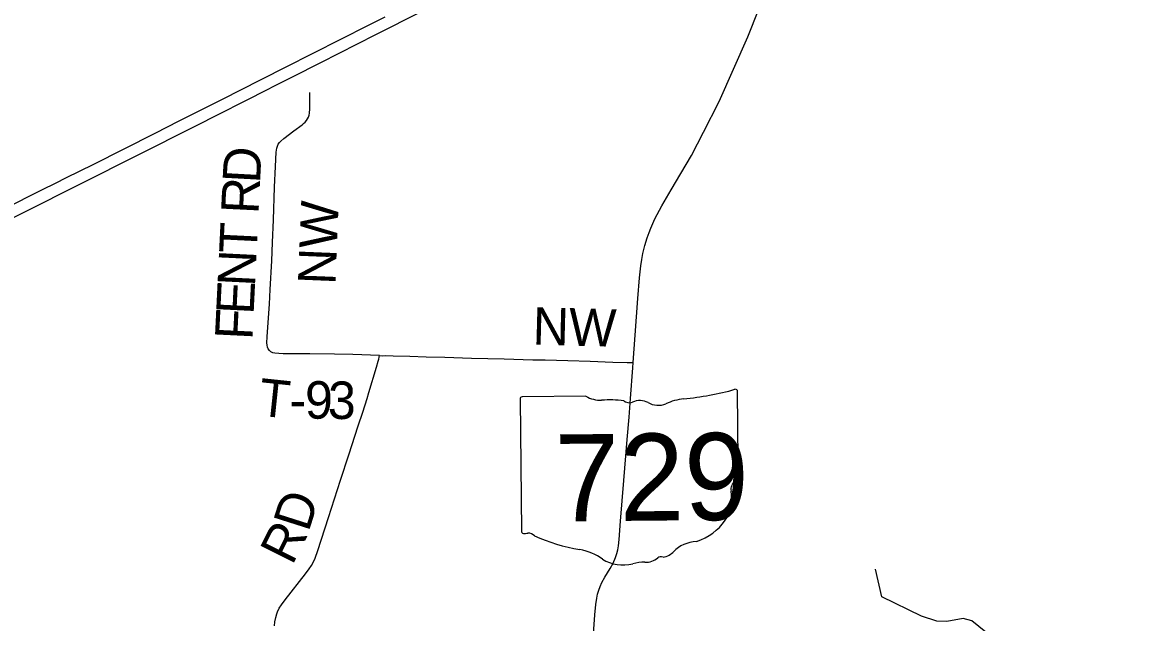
# Model space of a CAD drawing. Extents: x -51392 to 1635000, y 156707 to 696232.
# Drawn here: x 99291 to 108334, y 518897 to 523695 of the extents above; entities that cross this region are included whole.
import ezdxf

# ---------------------------------------------------------------- set-up
doc = ezdxf.new("R2010")
doc.units = 0
for name, color, linetype in [('GM_X_Interstate_Route', 7, 'Continuous'), ('GM_X_Minor_River', 7, 'Continuous'), ('GM_X_State_Route', 7, 'Continuous'), ('GM_X_State_Shield', 7, 'Continuous'), ('GM_X_Township_Road', 7, 'Continuous'), ('GM_X_Township_Road_Text', 7, 'Continuous')]:
    doc.layers.add(name, color=color, linetype=linetype)

msp = doc.modelspace()

# ---------------------------------------------------------------- linework, layer by layer
at = {"layer": 'GM_X_Interstate_Route'}
for points in [[(98288.9, 521664.8), (99299.2, 522175.3), (100672.6, 522866.2), (101261.3, 523166.3), (101288.6, 523180.1), (101449.2, 523261.5), (101677, 523376.8), (102116.2, 523598.7), (104332.5, 524719.6), (104554.7, 524832), (104752.9, 524932.3), (105459.5, 525289.9), (105516, 525318)], [(99138.8, 522202.1), (99451.2, 522359.7), (99553.2, 522411.1), (99642.5, 522456.9), (99854.4, 522560.5), (100352.1, 522811.7), (100543, 522908.6), (100906.6, 523091.8), (101026.5, 523152.4), (101392.8, 523339.4), (102056.5, 523673.7), (102190.2, 523741)]]:
    msp.add_lwpolyline(points, dxfattribs=at)
at = {"layer": 'GM_X_Minor_River'}
for points in [[(106161.9, 519100.6), (106111, 519322.7)], [(108342.2, 518202.7), (108302.5, 518267.1), (108220.7, 518345.9), (107975, 518510.1), (107850.9, 518565.1), (107718.6, 518588.1), (107533.7, 518555.4), (107475.5, 518559.9), (107253.2, 518631.7), (107175.2, 518672.3), (106881.8, 518911), (106813.7, 518929.6), (106681, 518904.5), (106600.8, 518907.1), (106478.6, 518948.1), (106161.9, 519100.6)]]:
    msp.add_lwpolyline(points, dxfattribs=at)
at = {"layer": 'GM_X_State_Route'}
msp.add_lwpolyline([(103852.3, 518729.9), (103868.1, 518959), (103875.4, 519040.9), (103882.5, 519089.9), (103889.5, 519122.2), (103898.6, 519154.1), (103910, 519185.2), (103923.8, 519215.2), (103947.7, 519258.7), (103989.9, 519329), (104012.6, 519372.2), (104031.7, 519417.1), (104042.1, 519447.8), (104050.3, 519479.1), (104056.6, 519511), (104062.5, 519559.4), (104073.7, 519706.5), (104098.9, 520033.6), (104126.4, 520360.4), (104140.5, 520540.2), (104152.3, 520687.4), (104171.5, 520932.6), (104174.6, 520976.2), (104190.7, 521194.3), (104211.7, 521488.7), (104224.9, 521652.2), (104235, 521750.3), (104242.1, 521799.2), (104251.8, 521847.7), (104266.5, 521911.5), (104285.9, 521974.6), (104300.8, 522015.7), (104314.5, 522051.3), (104330.1, 522088.7), (104347.5, 522124.3), (104402.3, 522229.6), (104478, 522357.8), (104554.3, 522486.7), (104639.1, 522632.9), (104737.4, 522817.8), (104861.8, 523064.3), (105090.7, 523580.8), (105178.9, 523801.9)], dxfattribs=at)
at = {"layer": 'GM_X_State_Shield'}
for p, q in [((105014.5, 520191.6), (105009.3, 520744.3)), ((103269.6, 520683.6), (103279.5, 519627)), ((103796.2, 520706.7), (103286.6, 520701.9)), ((105014.3, 520191.7), (105014.5, 520191.6))]:
    msp.add_line(p, q, dxfattribs=at)
for centre, major_axis, start_param, end_param in [((104376.2, 522152.8), (1845.4, 17.3), 4.814394, 5.042369), ((104990, 520746.4), (19.4, 0.2), 6.141152, 7.989035), ((103289.5, 520686), (20.2, 0.2), 1.712693, 3.28349), ((103916.4, 520830.5), (195.5, 1.8), 4.042523, 4.731795), ((103987.9, 520115.3), (702, 6.6), 1.404758, 1.657858), ((104141.8, 520699.5), (56.4, 0.5), 3.836095, 5.185415), ((104225.8, 520578.1), (117.3, 1.1), 0.950623, 2.079405), ((104375.6, 520747.1), (141.1, 1.3), 4.081561, 5.145723), ((104628.1, 520391.8), (371.3, 3.5), 1.699011, 2.107814), ((104993.9, 520189.2), (20.7, 0.2), 5.05454, 6.418171), ((105010.4, 520150.9), (30, 0.3), 1.883978, 3.671073), ((104820.3, 520079.3), (180, 1.7), 5.934695, 6.695948), ((105086.1, 519960.9), (130.9, 1.2), 2.387724, 3.262537), ((104500.9, 519885.1), (461.6, 4.3), 5.101752, 6.440018), ((103299.7, 519624.8), (20.3, 0.2), 3.00124, 4.508301), ((103301.7, 519733), (155.2, 1.5), 4.665946, 4.897461), ((103335.1, 519566.5), (56, 0.5), 0.519207, 1.627899), ((104032.7, 520522.5), (1332.6, 12.5), 4.195997, 4.488961), ((103648.2, 519155.7), (417, 3.9), 0.823519, 1.323587), ((104700.6, 519343.7), (252.8, 2.4), 1.647645, 2.488434), ((104095.3, 519568.4), (264.6, 2.5), 4.026481, 4.996735), ((104251.6, 519204.6), (217.4, 2), 1.495662, 1.94098), ((104268.3, 519490.9), (141, 1.3), 4.691044, 5.507374), ((104396.8, 519389.8), (39.7, 0.4), 1.147584, 2.315152), ((104378.5, 519534.9), (149.1, 1.4), 4.937069, 5.64225)]:
    msp.add_ellipse(centre, major_axis=major_axis, ratio=0.8, start_param=start_param, end_param=end_param, dxfattribs=at)
at = {"layer": 'GM_X_Township_Road'}
for points in [[(102144.7, 521031.3), (101932.4, 521041), (101784.6, 521043.2), (101587.4, 521045), (101488.7, 521045.4), (101373.8, 521046.8), (101340.7, 521047), (101308, 521050.4), (101292.1, 521054.7), (101277.4, 521061.9), (101264.9, 521072.1), (101255.4, 521085), (101249.1, 521099.9), (101245.9, 521115.9), (101244.9, 521132.3), (101247.3, 521181.9), (101256.2, 521296.6), (101266.2, 521444), (101272.3, 521558.9), (101283.2, 521788.6), (101288.5, 521936.4), (101297, 522116.9), (101306.3, 522379.7), (101314, 522543.8), (101320.3, 522658.6), (101324.3, 522691.3), (101328.4, 522707.2), (101334.9, 522722.2), (101344.7, 522735.3), (101356, 522747.3), (101380.8, 522768.7), (101459.3, 522828.4), (101525.6, 522877), (101538, 522887.7), (101549.8, 522899.2), (101560.7, 522911.5), (101570.5, 522924.6), (101578, 522939.2), (101582.3, 522955), (101585.1, 522971.2), (101588, 523003.9), (101588.5, 523086), (101587.9, 523135.4)], [(101305.9, 518870.4), (101309.5, 518903.1), (101315.2, 518935.4), (101324.1, 518966.8), (101329.6, 518982.2), (101344.2, 519011.4), (101361.6, 519039.1), (101390.5, 519079), (101553.4, 519284.9), (101582.6, 519324.5), (101600.6, 519351.8), (101616.4, 519380.5), (101629.8, 519410.4), (101652.2, 519472), (101738.5, 519737.2), (101833.3, 520034), (101899.4, 520236.7), (101975.8, 520470.5), (102011.4, 520579.5), (102046.7, 520688.4), (102061.1, 520735.4), (102121.8, 520939.6), (102135.6, 520986.8), (102139.5, 521002.8), (102142.4, 521018.2), (102144.7, 521031.3)], [(102144.7, 521031.3), (102166.8, 521030.7), (102191.4, 521030.9), (102255.3, 521029.9), (102387.9, 521026.2), (102519.1, 521022.4), (102666.6, 521018.1), (102879.7, 521011.6), (103142, 521005.5), (103371.5, 520998.8), (103469.9, 520996.5), (103650.1, 520991.8), (103830.4, 520986.3), (104010.7, 520979.9), (104125.4, 520976.8), (104141.8, 520976.7), (104174.6, 520976.2)]]:
    msp.add_lwpolyline(points, dxfattribs=at)

# ---------------------------------------------------------------- texts
at = {"layer": 'GM_X_State_Shield'}
msp.add_text('729', height=696.1, rotation=0.53855, dxfattribs=at).set_placement((103548.7, 519704))
at = {"layer": 'GM_X_Township_Road_Text'}
for s, rotation, p in [('D', 86.9188, (101189.3, 522405.5)), ('R', 87.20348, (101177.3, 522159.8)), ('NW', 87.65647, (101792.1, 521594.4)), ('T', 87.20681, (101161.9, 521843.3)), ('N', 87.21276, (101149.1, 521579.6)), ('E', 87.20681, (101138.1, 521355.4)), ('F', 87.21058, (101128.3, 521153.3)), ('NW', 358.47779, (103367.2, 521119.5)), ('T', 353.98159, (101169, 520552.9)), ('9', 359.46055, (101547.7, 520527.8)), ('3', 359.02604, (101730.4, 520526.1)), ('-', 0.07265, (101426.5, 520527.6)), ('D', 72.33441, (101577, 519613.4)), ('R', 63.36606, (101447.6, 519346.5))]:
    msp.add_text(s, height=300, rotation=rotation, dxfattribs=at).set_placement(p)

doc.saveas('drawing.dxf')
